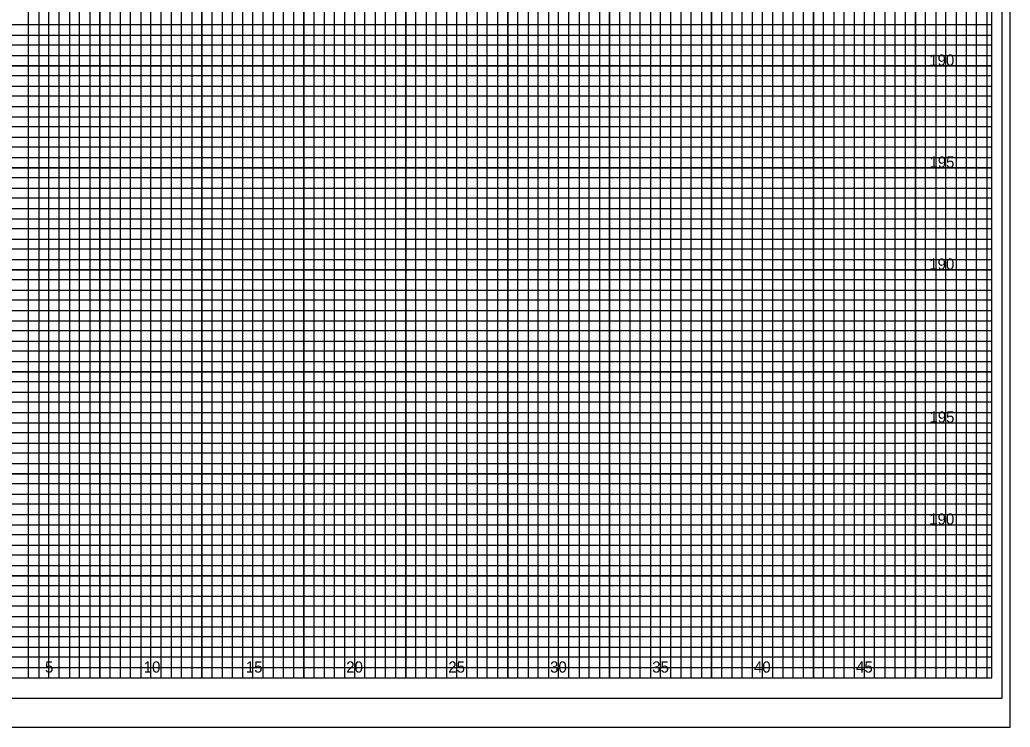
# Model space of a CAD drawing. Extents: x -4 to 103, y -2 to 67.
# Drawn here: x 54.82 to 103.4, y -2.43 to 32.25 of the extents above; entities that cross this region are included whole.
import ezdxf

# ---------------------------------------------------------------- set-up
doc = ezdxf.new("R2010")
doc.units = 0
for name, color, linetype in [('Exist XS Ground Line', 7, 'Continuous'), ('Old_Level_10', 7, 'Continuous'), ('Old_Level_16', 7, 'Continuous'), ('Old_Level_3', 7, 'Continuous'), ('Old_Level_5', 7, 'Continuous'), ('Old_Level_8', 7, 'Continuous'), ('Prop XS Dump Level', 7, 'Continuous'), ('Prop XS Finish Grade', 7, 'Continuous'), ('Prop XS Suitable Common Exc Shape', 7, 'Continuous')]:
    doc.layers.add(name, color=color, linetype=linetype)

msp = doc.modelspace()

# ---------------------------------------------------------------- linework, layer by layer
at = {"layer": 'Exist XS Ground Line'}
msp.add_lwpolyline([(103, 66), (-2.8, 66), (-2.8, -1), (103, -1)], close=True, dxfattribs=at)
at = {"layer": 'Old_Level_10'}
for p, q in [((56.25, 0), (56.25, 65)), ((58.75, 0), (58.75, 65)), ((61.25, 0), (61.25, 65)), ((63.75, 0), (63.75, 65)), ((66.25, 0), (66.25, 65)), ((68.75, 0), (68.75, 65)), ((71.25, 0), (71.25, 65)), ((73.75, 0), (73.75, 65)), ((91.25, 0), (91.25, 63.425)), ((93.75, 0), (93.75, 63.425)), ((96.25, 0), (96.25, 63.425)), ((98.75, 0), (98.75, 63.425)), ((101.25, 0), (101.25, 63.425)), ((76.25, 0), (76.25, 62)), ((78.75, 0), (78.75, 62)), ((81.25, 0), (81.25, 62)), ((83.75, 0), (83.75, 62)), ((86.25, 0), (86.25, 62)), ((88.75, 0), (88.75, 62)), ((0, 30), (102.5, 30)), ((0, 27.5), (102.5, 27.5)), ((0, 25), (102.5, 25)), ((0, 22.5), (102.5, 22.5)), ((0, 20), (102.5, 20)), ((0, 17.5), (102.5, 17.5)), ((0, 15), (102.5, 15)), ((0, 12.5), (102.5, 12.5)), ((0, 10), (102.5, 10)), ((0, 7.5), (102.5, 7.5)), ((0, 5), (102.5, 5)), ((0, 2.5), (102.5, 2.5))]:
    msp.add_line(p, q, dxfattribs=at)
at = {"layer": 'Old_Level_3'}
msp.add_line((-3.5, -2.425), (103.4, -2.425), dxfattribs=at)
at = {"layer": 'Old_Level_5'}
msp.add_lwpolyline([(103.4, 67.4), (-3.5, 67.4), (-3.5, -2.425), (103.4, -2.425)], close=True, dxfattribs=at)
at = {"layer": 'Old_Level_8'}
for points in [[(56.25, 0), (56.25, 65)], [(58.75, 65), (58.75, 0), (61.25, 0), (61.25, 65)], [(63.75, 65), (63.75, 0), (66.25, 0), (66.25, 65)], [(68.75, 65), (68.75, 0), (71.25, 0), (71.25, 65)], [(73.75, 65), (73.75, 0), (76.25, 0), (76.25, 62)], [(88.75, 62), (88.75, 0), (91.25, 0), (91.25, 63.425)], [(93.75, 63.425), (93.75, 0), (96.25, 0), (96.25, 63.425)], [(98.75, 63.425), (98.75, 0), (101.25, 0), (101.25, 63.425)], [(78.75, 62), (78.75, 0), (81.25, 0), (81.25, 62)], [(83.75, 62), (83.75, 0), (86.25, 0), (86.25, 62)], [(0, 27.5), (102.5, 27.5), (102.5, 30), (0, 30)], [(0, 22.5), (102.5, 22.5), (102.5, 25), (0, 25)], [(0, 17.5), (102.5, 17.5), (102.5, 20), (0, 20)], [(0, 12.5), (102.5, 12.5), (102.5, 15), (0, 15)], [(0, 7.5), (102.5, 7.5), (102.5, 10), (0, 10)], [(0, 2.5), (102.5, 2.5), (102.5, 5), (0, 5)]]:
    msp.add_lwpolyline(points, dxfattribs=at)
at = {"layer": 'Prop XS Dump Level'}
msp.add_lwpolyline([(102.5, 65), (0, 65), (0, 0), (102.5, 0)], close=True, dxfattribs=at)
at = {"layer": 'Prop XS Finish Grade'}
for points in [[(54.75, 0), (55.25, 0), (55.25, 65)], [(55.75, 65), (55.75, 0), (56.75, 0), (56.75, 65)], [(57.25, 65), (57.25, 0), (57.75, 0), (57.75, 65)], [(58.25, 65), (58.25, 0), (59.25, 0), (59.25, 65)], [(59.75, 65), (59.75, 0), (60.25, 0), (60.25, 65)], [(60.75, 65), (60.75, 0), (61.75, 0), (61.75, 65)], [(62.25, 65), (62.25, 0), (62.75, 0), (62.75, 65)], [(63.25, 65), (63.25, 0), (64.25, 0), (64.25, 65)], [(64.75, 65), (64.75, 0), (65.25, 0), (65.25, 65)], [(65.75, 65), (65.75, 0), (66.75, 0), (66.75, 65)], [(67.25, 65), (67.25, 0), (67.75, 0), (67.75, 65)], [(68.25, 65), (68.25, 0), (69.25, 0), (69.25, 65)], [(69.75, 65), (69.75, 0), (70.25, 0), (70.25, 65)], [(70.75, 65), (70.75, 0), (71.75, 0), (71.75, 65)], [(72.25, 65), (72.25, 0), (72.75, 0), (72.75, 65)], [(73.25, 65), (73.25, 0), (74.25, 0), (74.25, 62)], [(89.75, 62), (89.75, 0), (90.25, 0), (90.25, 63.425)], [(90.75, 63.425), (90.75, 0), (91.75, 0), (91.75, 63.425)], [(92.25, 63.425), (92.25, 0), (92.75, 0), (92.75, 63.425)], [(93.25, 63.425), (93.25, 0), (94.25, 0), (94.25, 63.425)], [(94.75, 63.425), (94.75, 0), (95.25, 0), (95.25, 63.425)], [(95.75, 63.425), (95.75, 0), (96.75, 0), (96.75, 63.425)], [(97.25, 63.425), (97.25, 0), (97.75, 0), (97.75, 63.425)], [(98.25, 63.425), (98.25, 0), (99.25, 0), (99.25, 63.425)], [(99.75, 63.425), (99.75, 0), (100.25, 0), (100.25, 63.425)], [(100.25, 63.425), (100.75, 63.425), (100.75, 0), (101.75, 0), (101.75, 63.425), (102.25, 63.425), (102.25, 0)], [(74.75, 62), (74.75, 0), (75.25, 0), (75.25, 62)], [(75.75, 62), (75.75, 0), (76.75, 0), (76.75, 62)], [(77.25, 62), (77.25, 0), (77.75, 0), (77.75, 62)], [(78.25, 62), (78.25, 0), (79.25, 0), (79.25, 62)], [(79.75, 62), (79.75, 0), (80.25, 0), (80.25, 62)], [(80.75, 62), (80.75, 0), (81.75, 0), (81.75, 62)], [(82.25, 62), (82.25, 0), (82.75, 0), (82.75, 62)], [(83.25, 62), (83.25, 0), (84.25, 0), (84.25, 62)], [(84.75, 62), (84.75, 0), (85.25, 0), (85.25, 62)], [(85.75, 62), (85.75, 0), (86.75, 0), (86.75, 62)], [(87.25, 62), (87.25, 0), (87.75, 0), (87.75, 62)], [(88.25, 62), (88.25, 0), (89.25, 0), (89.25, 62)], [(0, 31.5), (102.5, 31.5), (102.5, 32), (0, 32)], [(0, 30.5), (102.5, 30.5), (102.5, 31), (0, 31)], [(0, 29), (102.5, 29), (102.5, 29.5), (0, 29.5)], [(0, 28), (102.5, 28), (102.5, 28.5), (0, 28.5)], [(0, 26.5), (102.5, 26.5), (102.5, 27), (0, 27)], [(0, 25.5), (102.5, 25.5), (102.5, 26), (0, 26)], [(0, 24), (102.5, 24), (102.5, 24.5), (0, 24.5)], [(0, 23), (102.5, 23), (102.5, 23.5), (0, 23.5)], [(0, 21.5), (102.5, 21.5), (102.5, 22), (0, 22)], [(0, 20.5), (102.5, 20.5), (102.5, 21), (0, 21)], [(0, 19), (102.5, 19), (102.5, 19.5), (0, 19.5)], [(0, 18), (102.5, 18), (102.5, 18.5), (0, 18.5)], [(0, 16.5), (102.5, 16.5), (102.5, 17), (0, 17)], [(0, 15.5), (102.5, 15.5), (102.5, 16), (0, 16)], [(0, 14), (102.5, 14), (102.5, 14.5), (0, 14.5)], [(0, 13), (102.5, 13), (102.5, 13.5), (0, 13.5)], [(0, 11.5), (102.5, 11.5), (102.5, 12), (0, 12)], [(0, 10.5), (102.5, 10.5), (102.5, 11), (0, 11)], [(0, 9), (102.5, 9), (102.5, 9.5), (0, 9.5)], [(0, 8), (102.5, 8), (102.5, 8.5), (0, 8.5)], [(0, 6.5), (102.5, 6.5), (102.5, 7), (0, 7)], [(0, 5.5), (102.5, 5.5), (102.5, 6), (0, 6)], [(0, 4), (102.5, 4), (102.5, 4.5), (0, 4.5)], [(0, 3), (102.5, 3), (102.5, 3.5), (0, 3.5)], [(0, 1.5), (102.5, 1.5), (102.5, 2), (0, 2)], [(0, 0.5), (102.5, 0.5), (102.5, 1), (0, 1)]]:
    msp.add_lwpolyline(points, dxfattribs=at)

# ---------------------------------------------------------------- texts
at = {"layer": 'Old_Level_16'}
for s, p in [('5', (56.0574, 0.25)), ('10', (60.8971, 0.25)), ('15', (65.9057, 0.25)), ('20', (70.8312, 0.25)), ('25', (75.8399, 0.25)), ('30', (80.8312, 0.25)), ('35', (85.8399, 0.25)), ('40', (90.8313, 0.25)), ('45', (95.8399, 0.25))]:
    msp.add_text(s, height=0.55, dxfattribs=at).set_placement(p)
at = {"layer": 'Prop XS Suitable Common Exc Shape'}
for s, p in [('190', (99.4296, 30)), ('195', (99.4383, 25)), ('190', (99.4296, 20)), ('195', (99.4383, 12.5)), ('190', (99.4296, 7.5))]:
    msp.add_text(s, height=0.55, dxfattribs=at).set_placement(p)

doc.saveas('drawing.dxf')
